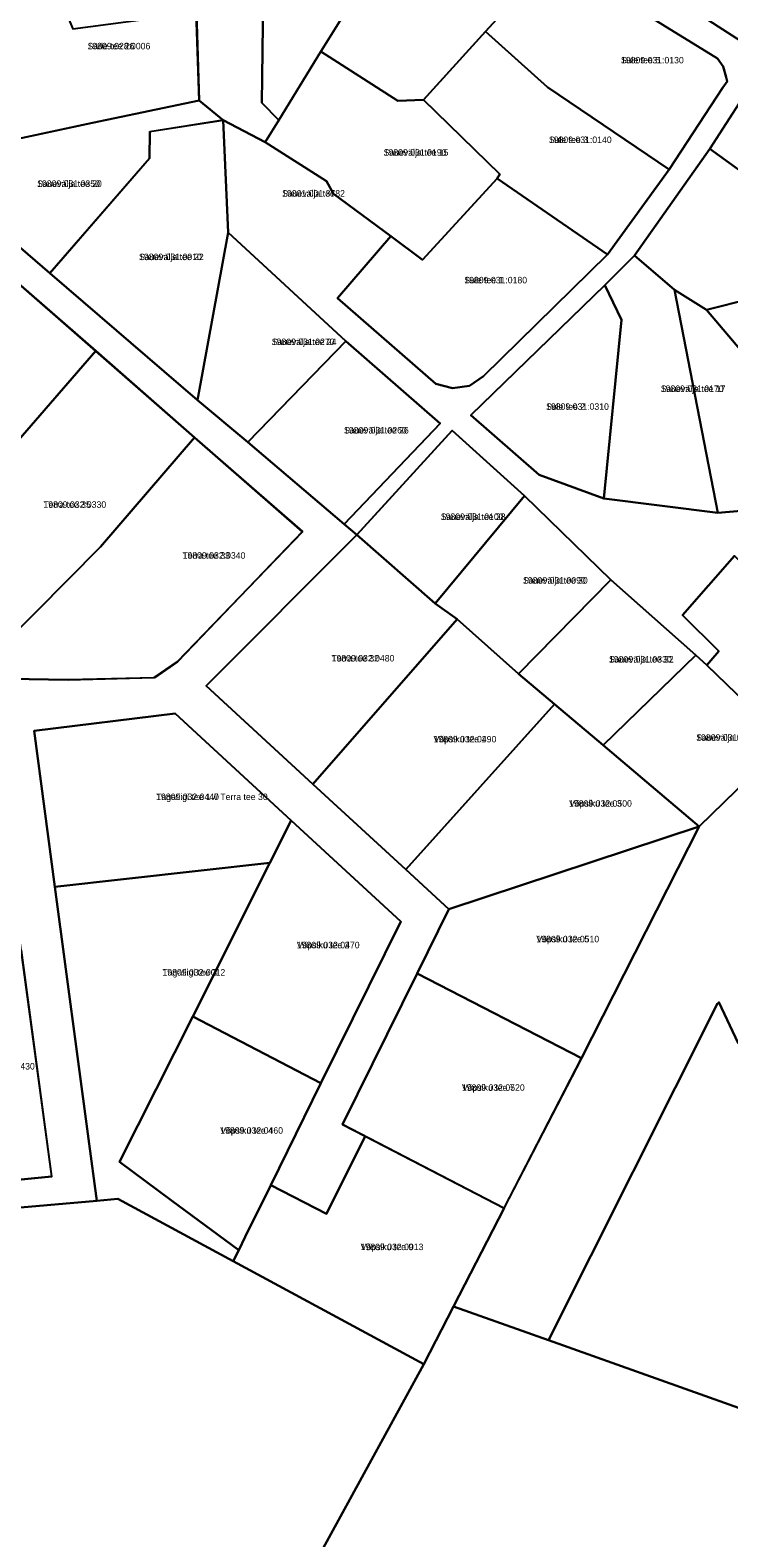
# Model space of a CAD drawing. Extents: x 516875 to 535633, y 6574491 to 6593094.
# Drawn here: x 521648.2 to 521809.5, y 6588311.2 to 6588659.7 of the extents above; entities that cross this region are included whole.
import ezdxf

# ---------------------------------------------------------------- set-up
doc = ezdxf.new("R2010")
doc.units = 0
for name, color, linetype in [('L_AADRESS', 7, 'Continuous'), ('PIIR', 7, 'Continuous'), ('TUNNUS', 7, 'Continuous')]:
    doc.layers.add(name, color=color, linetype=linetype)

msp = doc.modelspace()

# ---------------------------------------------------------------- linework, layer by layer
at = {"layer": 'PIIR'}
for points in [[(521701.97, 6588666.89), (521726.13, 6588703.92), (521740.2, 6588694.73), (521715.24, 6588654.72), (521705.56, 6588638.88), (521701.69, 6588642.87)], [(521715.24, 6588654.72), (521740.2, 6588694.73), (521768.99, 6588676.54), (521753.3, 6588659.4), (521738.96, 6588643.55), (521733.04, 6588643.34)], [(521792.34, 6588670.05), (521806.39, 6588691.14), (521811.89, 6588687.78), (521828.99, 6588676.38), (521814.85, 6588655.55)], [(521635.57, 6588669.71), (521645.98, 6588675.4), (521650.36, 6588677.81), (521657.98, 6588660.01), (521686.54, 6588663.79), (521687.16, 6588643.42), (521662.53, 6588638.23), (521636.65, 6588632.7)], [(521768.99, 6588676.54), (521806.87, 6588653.15), (521808.19, 6588651.25), (521808.9, 6588648.85), (521809.11, 6588647.83), (521808.15, 6588646.42), (521795.73, 6588627.46), (521767.59, 6588646.53), (521753.3, 6588659.4)], [(521738.96, 6588643.55), (521753.3, 6588659.4), (521767.59, 6588646.53), (521795.73, 6588627.46), (521781.51, 6588607.8), (521756, 6588625.41), (521756.6, 6588626.43)], [(521705.56, 6588638.88), (521715.24, 6588654.72), (521733.04, 6588643.34), (521738.96, 6588643.55), (521756.6, 6588626.43), (521756, 6588625.41), (521738.75, 6588606.64), (521731.44, 6588612.08), (521718.24, 6588621.88), (521716.62, 6588624.77), (521702.45, 6588633.81)], [(521812.66, 6588643.98), (521805.09, 6588632.22), (521787.69, 6588607.6), (521780.83, 6588600.74), (521749.9, 6588570.67), (521765.69, 6588556.88), (521780.6, 6588551.45), (521806.98, 6588548.11), (521816.81, 6588548.97), (521834.35, 6588559.6), (521848.59, 6588575.07), (521873.21, 6588599.07), (521873.65, 6588604.72), (521859, 6588619.13), (521817.82, 6588646.36)], [(521805.09, 6588632.22), (521812.66, 6588643.98), (521817.82, 6588646.36), (521859, 6588619.13), (521842.72, 6588604.96)], [(521636.61, 6588632.74), (521662.53, 6588638.23), (521687.16, 6588643.42), (521692.7, 6588638.85), (521675.78, 6588636.22), (521675.71, 6588630.06), (521652.69, 6588603.5), (521622.12, 6588629.84)], [(521675.81, 6588636.25), (521692.7, 6588638.85), (521693.91, 6588612.9), (521686.83, 6588574.17), (521652.69, 6588603.5), (521675.73, 6588630.09)], [(521787.69, 6588607.6), (521805.09, 6588632.22), (521842.72, 6588604.96), (521824.49, 6588600.1), (521804.33, 6588595.07), (521796.95, 6588599.64)], [(521719.16, 6588597.77), (521731.44, 6588612.08), (521738.75, 6588606.64), (521756, 6588625.41), (521781.51, 6588607.8), (521752.88, 6588579.72), (521749.63, 6588577.52), (521745.68, 6588576.92), (521741.85, 6588577.93)], [(521686.83, 6588574.17), (521693.91, 6588612.9), (521721.05, 6588587.84), (521698.41, 6588564.48)], [(521780.83, 6588600.74), (521787.69, 6588607.6), (521796.95, 6588599.64), (521806.98, 6588548.11), (521780.6, 6588551.45), (521784.7, 6588592.76)], [(521600.35, 6588558.85), (521641.26, 6588604.83), (521663.3, 6588585.55), (521622.88, 6588538.98)], [(521749.9, 6588570.67), (521780.83, 6588600.74), (521784.7, 6588592.76), (521780.6, 6588551.45), (521765.69, 6588556.88)], [(521806.98, 6588548.11), (521796.95, 6588599.64), (521804.33, 6588595.07), (521834.35, 6588559.6), (521816.81, 6588548.97)], [(521834.35, 6588559.6), (521804.33, 6588595.07), (521824.49, 6588600.1), (521848.59, 6588575.07)], [(521616.28, 6588529.95), (521622.88, 6588538.98), (521663.3, 6588585.55), (521686.13, 6588565.57), (521664.39, 6588540.27), (521634.3, 6588509.94)], [(521698.41, 6588564.48), (521721.05, 6588587.84), (521742.86, 6588568.77), (521720.69, 6588545.48)], [(521676.85, 6588510.03), (521656.9, 6588509.51), (521634.3, 6588509.94), (521664.39, 6588540.27), (521686.13, 6588565.57), (521711.04, 6588543.8), (521682.19, 6588513.73)], [(521723.63, 6588543.02), (521745.62, 6588567.14), (521762.33, 6588552.07), (521741.68, 6588527.17)], [(521741.68, 6588527.17), (521762.33, 6588552.07), (521782.26, 6588532.62), (521760.95, 6588510.89), (521746.73, 6588523.55)], [(521746.73, 6588523.55), (521713.41, 6588485.41), (521688.82, 6588508.16), (521723.63, 6588543.02), (521741.68, 6588527.17)], [(521798.78, 6588524.51), (521810.8, 6588538.17), (521838.26, 6588510.21), (521822.72, 6588495.19), (521804.42, 6588512.93), (521807.19, 6588516.18)], [(521760.95, 6588510.89), (521782.26, 6588532.62), (521801.87, 6588515.27), (521780.48, 6588494.46), (521769.21, 6588503.93)], [(521713.41, 6588485.41), (521746.73, 6588523.55), (521760.95, 6588510.89), (521769.21, 6588503.93), (521734.9, 6588465.67)], [(521780.48, 6588494.46), (521801.87, 6588515.27), (521804.42, 6588512.93), (521822.72, 6588495.19), (521802.64, 6588475.66)], [(521681.62, 6588501.78), (521708.39, 6588477.04), (521703.53, 6588467.24), (521653.86, 6588461.74), (521649.09, 6588497.73)], [(521734.9, 6588465.67), (521769.21, 6588503.93), (521780.48, 6588494.46), (521802.64, 6588475.66), (521744.81, 6588456.53)], [(521578.99, 6588498.53), (521585.38, 6588440.81), (521591.22, 6588388.52), (521621.86, 6588391.71), (521653.14, 6588394.78), (521646.07, 6588447.07), (521639.38, 6588496.37), (521610.38, 6588493.89), (521609.37, 6588500.98)], [(521703.53, 6588467.24), (521708.39, 6588477.04), (521733.79, 6588453.66), (521715.31, 6588416.3), (521685.68, 6588431.74)], [(521744.81, 6588456.53), (521802.64, 6588475.66), (521775.47, 6588422.09), (521737.53, 6588441.67)], [(521653.86, 6588461.74), (521703.53, 6588467.24), (521685.68, 6588431.74), (521668.76, 6588398.18), (521680.77, 6588389.25), (521696.31, 6588377.7), (521695.06, 6588375.17), (521668.37, 6588389.58), (521663.55, 6588389.16), (521661.65, 6588403.44)], [(521616.34, 6588444.25), (521646.04, 6588447.07), (521653.1, 6588394.78), (521621.84, 6588391.69)], [(521737.53, 6588441.67), (521775.47, 6588422.09), (521757.57, 6588387.44), (521720.29, 6588406.74)], [(521767.83, 6588356.93), (521806.88, 6588434.72), (521807.21, 6588435.06), (521811.68, 6588425.58), (521854.43, 6588389.09), (521948.1, 6588337.93), (521923.51, 6588301.46)], [(521685.68, 6588431.74), (521715.31, 6588416.3), (521703.73, 6588392.77), (521697.84, 6588380.81), (521696.31, 6588377.7), (521680.77, 6588389.25), (521668.76, 6588398.18)], [(521703.73, 6588392.77), (521716.62, 6588386.1), (521725.48, 6588404.06), (521757.62, 6588387.42), (521745.91, 6588364.74), (521739.03, 6588351.41), (521695.06, 6588375.17), (521696.31, 6588377.7), (521697.84, 6588380.81)], [(521611.88, 6588234.23), (521596.92, 6588242.31), (521590.65, 6588312.15), (521588.28, 6588341.15), (521586.28, 6588365.65), (521584.92, 6588382.26), (521663.55, 6588389.16), (521668.37, 6588389.58), (521695.06, 6588375.17), (521739.03, 6588351.41), (521660.34, 6588207.31), (521660.3, 6588207.32), (521657.67, 6588207.99), (521654.73, 6588209.24), (521633.08, 6588222.19)], [(521662.26, 6588206.2), (521660.34, 6588207.31), (521739.03, 6588351.41), (521745.91, 6588364.74), (521767.83, 6588356.93), (521923.51, 6588301.46), (521940.7, 6588295.34), (521911.84, 6588255.77), (521895.87, 6588232.3), (521877.19, 6588214.89), (521863.3, 6588195.38), (521848.98, 6588175.48), (521848.19, 6588174.37), (521846.41, 6588175.69), (521831.14, 6588153.76), (521815.1, 6588130.16), (521810.15, 6588122.86), (521677.48, 6588197.33)]]:
    msp.add_lwpolyline(points, close=True, dxfattribs=at)
for points in [[(521810.8, 6588538.17), (521798.78, 6588524.51), (521807.19, 6588516.18), (521804.42, 6588512.93), (521801.87, 6588515.27), (521782.26, 6588532.62), (521762.33, 6588552.07), (521745.62, 6588567.14), (521723.63, 6588543.02), (521720.69, 6588545.48), (521742.86, 6588568.77), (521721.05, 6588587.84), (521693.91, 6588612.9), (521692.7, 6588638.85), (521702.45, 6588633.81), (521716.62, 6588624.77), (521718.24, 6588621.88), (521731.44, 6588612.08), (521719.16, 6588597.77), (521741.85, 6588577.93), (521745.68, 6588576.92), (521749.63, 6588577.52), (521752.88, 6588579.72), (521781.51, 6588607.8), (521795.73, 6588627.46), (521808.15, 6588646.42), (521809.11, 6588647.83), (521808.9, 6588648.85), (521808.19, 6588651.25), (521806.87, 6588653.15), (521768.99, 6588676.54)], [(521792.34, 6588670.05), (521814.85, 6588655.55)], [(521701.97, 6588666.89), (521701.69, 6588642.87), (521705.56, 6588638.88), (521702.45, 6588633.81), (521692.7, 6588638.85), (521687.16, 6588643.42), (521686.51, 6588663.81)], [(521622.12, 6588629.84), (521652.69, 6588603.5), (521686.83, 6588574.17), (521698.41, 6588564.48), (521720.69, 6588545.48), (521723.63, 6588543.02), (521688.82, 6588508.16), (521713.41, 6588485.41), (521734.9, 6588465.67), (521744.81, 6588456.53), (521737.53, 6588441.67), (521720.29, 6588406.74), (521725.48, 6588404.06), (521716.62, 6588386.1), (521703.73, 6588392.77), (521715.31, 6588416.3), (521733.79, 6588453.66), (521708.39, 6588477.04), (521681.62, 6588501.78), (521649.09, 6588497.73), (521653.86, 6588461.74), (521661.65, 6588403.44), (521663.55, 6588389.16), (521584.92, 6588382.26)], [(521634.32, 6588509.92), (521656.89, 6588509.55), (521676.82, 6588510.06), (521682.18, 6588513.76), (521711.04, 6588543.77), (521686.14, 6588565.54), (521663.3, 6588585.53), (521641.25, 6588604.8)], [(521811.68, 6588425.58), (521807.21, 6588435.06), (521806.88, 6588434.72), (521767.83, 6588356.93), (521745.91, 6588364.74), (521757.62, 6588387.42), (521775.47, 6588422.09), (521802.64, 6588475.66), (521822.72, 6588495.19)]]:
    msp.add_lwpolyline(points, dxfattribs=at)

# ---------------------------------------------------------------- texts
at = {"layer": 'L_AADRESS'}
for s, p in [('Säde tee 26', (521661.4, 6588655.25)), ('Sule tee 5', (521784.59, 6588652)), ('Sule tee 3', (521767.94, 6588633.6)), ('Sauevälja tee 15', (521729.79, 6588630.68)), ('Sauevälja tee 20', (521649.76, 6588623.46)), ('Sauevälja tee', (521706.34, 6588621.21)), ('Sauevälja tee 22', (521673.3, 6588606.54)), ('Sule tee 1', (521748.41, 6588601.17)), ('Sauevälja tee 24', (521703.94, 6588586.91)), ('Sauevälja tee 17', (521793.79, 6588576.07)), ('Sule tee 2', (521767.3, 6588571.94)), ('Sauevälja tee 26', (521720.63, 6588566.47)), ('Terra tee 35', (521651.21, 6588549.3)), ('Sauevälja tee 28', (521742.98, 6588546.49)), ('Terra tee 33', (521683.36, 6588537.54)), ('Sauevälja tee 30', (521761.97, 6588531.78)), ('Terra tee 32', (521717.77, 6588513.78)), ('Sauevälja tee 32', (521781.82, 6588513.54)), ('Võpsiku tee 1', (521741.31, 6588495.08)), ('Sauevälja tee 34', (521801.97, 6588495.46)), ('Tagatiigi tee 1 // Terra tee 30', (521677.24, 6588481.76)), ('Võpsiku tee 3', (521772.61, 6588480.23)), ('Võpsiku tee 5', (521765.06, 6588448.88)), ('Võpsiku tee 2', (521709.73, 6588447.5)), ('Tagatiigi tee 3', (521678.7, 6588441.19)), ('Võpsiku tee 7', (521747.86, 6588414.56)), ('Võpsiku tee 4', (521692.04, 6588404.65)), ('Võpsiku tee 9', (521724.47, 6588377.74))]:
    msp.add_text(s, height=1.5, dxfattribs=at).set_placement(p)
at = {"layer": 'TUNNUS'}
for s, p in [('19809:028:0006', (521661.4, 6588655.25)), ('19809:031:0130', (521784.59, 6588652)), ('19809:031:0140', (521767.94, 6588633.6)), ('19809:031:0190', (521729.79, 6588630.68)), ('19809:031:0350', (521649.76, 6588623.46)), ('19801:001:3782', (521706.34, 6588621.21)), ('19809:031:0010', (521673.3, 6588606.54)), ('19809:031:0180', (521748.41, 6588601.17)), ('19809:031:0270', (521703.94, 6588586.91)), ('19809:031:0170', (521793.79, 6588576.07)), ('19809:031:0310', (521767.3, 6588571.94)), ('19809:031:0260', (521720.63, 6588566.47)), ('19809:032:0330', (521651.21, 6588549.3)), ('19809:031:0100', (521742.98, 6588546.49)), ('19809:032:0340', (521683.36, 6588537.54)), ('19809:031:0090', (521761.97, 6588531.78)), ('19809:032:0480', (521717.77, 6588513.78)), ('19809:031:0330', (521781.82, 6588513.54)), ('19809:032:0490', (521741.31, 6588495.08)), ('19809:031:0250', (521801.97, 6588495.46)), ('19809:032:0440', (521677.24, 6588481.76)), ('19809:032:0500', (521772.61, 6588480.23)), ('19809:032:0510', (521765.06, 6588448.88)), ('19809:032:0470', (521709.73, 6588447.5)), ('19809:032:0012', (521678.7, 6588441.19)), ('19809:032:0430', (521634.72, 6588419.48)), ('19809:032:0520', (521747.86, 6588414.56)), ('19809:032:0460', (521692.04, 6588404.65)), ('19809:032:0013', (521724.47, 6588377.74))]:
    msp.add_text(s, height=1.5, dxfattribs=at).set_placement(p)

doc.saveas('drawing.dxf')
